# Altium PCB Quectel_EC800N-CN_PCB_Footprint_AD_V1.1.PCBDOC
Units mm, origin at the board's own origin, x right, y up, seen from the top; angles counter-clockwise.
Board outline 152.4 x 101.6 mm, 2 copper layers (Top Layer, Bottom Layer); 1 components, 0 nets, 94 pads, 0 vias.
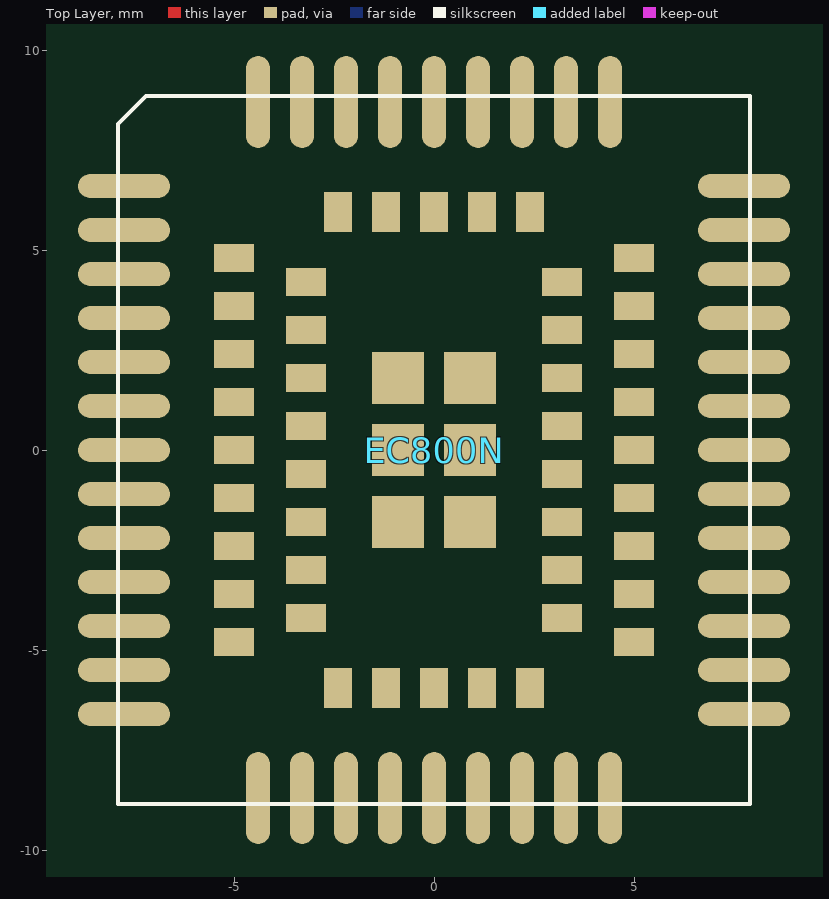
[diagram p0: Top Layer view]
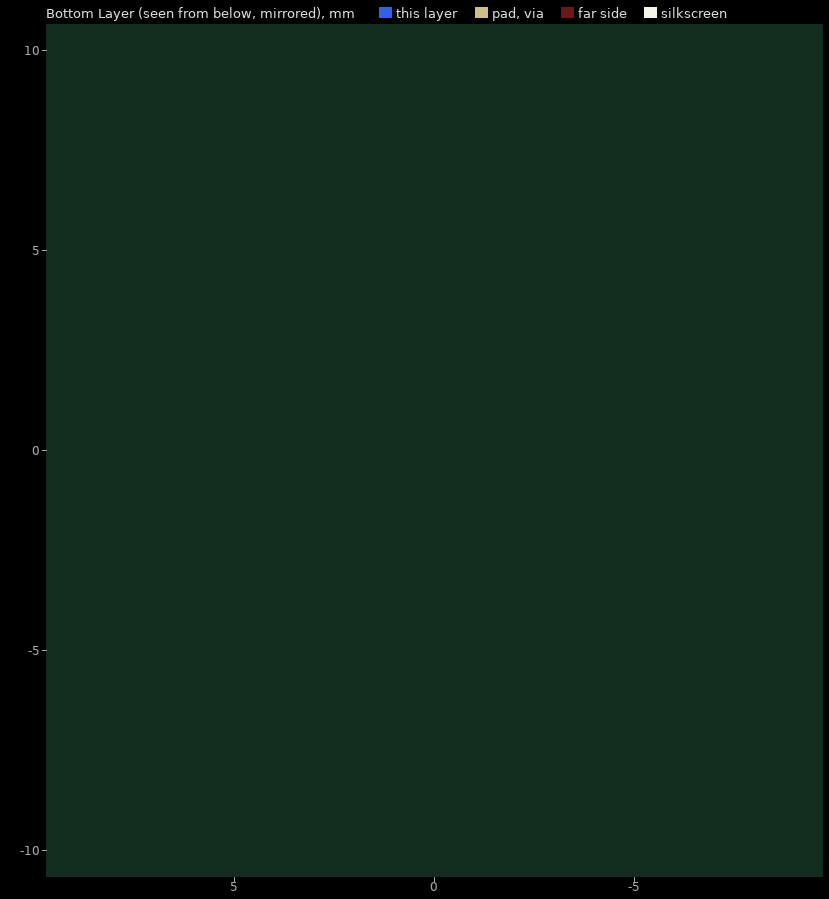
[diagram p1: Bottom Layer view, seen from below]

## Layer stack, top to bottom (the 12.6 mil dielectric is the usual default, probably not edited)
Top Solder: solder mask 0.0102, Solder Resist, Dk 3.5
Top Layer: signal copper 0.0356
Dielectric1: dielectric 0.32, FR-4, Dk 4.8
Bottom Layer: signal copper 0.0356
Bottom Solder: solder mask 0.0102, Solder Resist, Dk 3.5

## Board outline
-50.546,-45.466 101.854,-45.466 101.854,56.134 -50.546,56.134

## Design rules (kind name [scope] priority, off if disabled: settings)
Clearance [All] p1: gap=0.254 ignorepadtopadclearanceinfootprint=FALSE except(0: Arc-Hole Track-Hole SMDPad-Hole THPad-Hole Via-Hole Fill-Hole Poly-Hole Region-Hole Text-Hole)
FabricationTestPointUsage TestPointUsage [All] p1: valid=0 allowmultiple=FALSE
FabricationTestpoint Testpoint [All] p1: side=3 testpointundercomponent=TRUE minsize=1.016 maxsize=2.54 preferedsize=1.524 minholesize=0 maxholesize=1.016 preferedholesize=0.813 testpointgrid=0.025 allowsidetop=TRUE allowsidebottom=TRUE usegrid=TRUE gridtolerance=0
PolygonConnect [All] p1: connectstyle=Relief reliefconductorwidth=0.254 reliefentries=4 polygonreliefangle="90 Angle" airgapwidth=0.254
RoutingVias [All] p1: holewidth=0.711 width=1.27 viastyle="Through Hole" minholewidth=0.711 minwidth=1.27 maxholewidth=0.711 maxwidth=1.27
SolderMaskExpansion [All] p1: expansion=0.102
Width [All] p1: maxlimit=0.254 minlimit=0.254 preferedwidth=0.254
28 further rules are at their usual default settings.

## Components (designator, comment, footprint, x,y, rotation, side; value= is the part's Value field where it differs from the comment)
EC800N "Comment" EC800N 0,0 r0 top

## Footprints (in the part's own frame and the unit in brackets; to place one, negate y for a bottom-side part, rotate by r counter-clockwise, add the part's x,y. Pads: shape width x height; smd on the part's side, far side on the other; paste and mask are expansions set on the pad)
EC800N [mm] "EC800N-CN Moudle 94PIN 15.8X17.7mm H2.4mm RO"
  oval 2.3x0.6 smd mask+0.05: 1(-7.75,6.6) 2(-7.75,5.5) 3(-7.75,4.4) 4(-7.75,3.3) 5(-7.75,2.2) 6(-7.75,1.1) 7(-7.75,0) 8(-7.75,-1.1) 9(-7.75,-2.2) 10(-7.75,-3.3) 11(-7.75,-4.4) 12(-7.75,-5.5) 13(-7.75,-6.6) 23(7.75,-6.6) 24(7.75,-5.5) 25(7.75,-4.4) 26(7.75,-3.3) 27(7.75,-2.2) 28(7.75,-1.1) 29(7.75,0) 30(7.75,1.1) 31(7.75,2.2) 32(7.75,3.3) 33(7.75,4.4) 34(7.75,5.5) 35(7.75,6.6)
  oval 0.6x2.3 smd mask+0.05: 14(-4.4,-8.7) 15(-3.3,-8.7) 16(-2.2,-8.7) 17(-1.1,-8.7) 18(0,-8.7) 19(1.1,-8.7) 20(2.2,-8.7) 21(3.3,-8.7) 22(4.4,-8.7) 36(4.4,8.7) 37(3.3,8.7) 38(2.2,8.7) 39(1.1,8.7) 40(0,8.7) 41(-1.1,8.7) 42(-2.2,8.7) 43(-3.3,8.7) 44(-4.4,8.7)
  rect 1x0.7 smd mask+0.05: 45(-5,4.8) 46(-5,3.6) 47(-5,2.4) 48(-5,1.2) 49(-5,0) 50(-5,-1.2) 51(-5,-2.4) 52(-5,-3.6) 53(-5,-4.8) 59(5,-4.8) 60(5,-3.6) 61(5,-2.4) 62(5,-1.2) 63(5,0) 64(5,1.2) 65(5,2.4) 66(5,3.6) 67(5,4.8) 73(-3.2,4.2) 74(-3.2,3) 75(-3.2,1.8) 76(-3.2,0.6) 77(-3.2,-0.6) 78(-3.2,-1.8) 79(-3.2,-3) 80(-3.2,-4.2) 81(3.2,-4.2) 82(3.2,-3) 83(3.2,-1.8) 84(3.2,-0.6) 85(3.2,0.6) 86(3.2,1.8) 87(3.2,3) 88(3.2,4.2)
  rect 0.7x1 smd mask+0.05: 54(-2.4,-5.95) 55(-1.2,-5.95) 56(0,-5.95) 57(1.2,-5.95) 58(2.4,-5.95) 68(2.4,5.95) 69(1.2,5.95) 70(0,5.95) 71(-1.2,5.95) 72(-2.4,5.95)
  rect 1.3x1.3 smd mask+0.05: 89(-0.9,1.8) 90(-0.9,0) 91(-0.9,-1.8) 92(0.9,-1.8) 93(0.9,0) 94(0.9,1.8)
  silkscreen extent -7.9,-8.85 7.9,8.85

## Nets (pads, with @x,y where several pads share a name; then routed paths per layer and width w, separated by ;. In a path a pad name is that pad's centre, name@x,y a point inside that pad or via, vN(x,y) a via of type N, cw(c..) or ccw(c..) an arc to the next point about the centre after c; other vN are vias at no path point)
pads on no net: EC800N.1 EC800N.2 EC800N.3 EC800N.4 EC800N.5 EC800N.6 EC800N.7 EC800N.8 EC800N.9 EC800N.10 EC800N.11 EC800N.12 EC800N.13 EC800N.14 EC800N.15 EC800N.16 EC800N.17 EC800N.18 EC800N.19 EC800N.20 EC800N.21 EC800N.22 EC800N.23 EC800N.24 EC800N.25 EC800N.26 EC800N.27 EC800N.28 EC800N.29 EC800N.30 EC800N.31 EC800N.32 EC800N.33 EC800N.34 EC800N.35 EC800N.36 EC800N.37 EC800N.38 EC800N.39 EC800N.40 EC800N.41 EC800N.42 EC800N.43 EC800N.44 EC800N.45 EC800N.46 EC800N.47 EC800N.48 EC800N.49 EC800N.50 EC800N.51 EC800N.52 EC800N.53 EC800N.54 EC800N.55 EC800N.56 EC800N.57 EC800N.58 EC800N.59 EC800N.60 EC800N.61 EC800N.62 EC800N.63 EC800N.64 EC800N.65 EC800N.66 EC800N.67 EC800N.68 EC800N.69 EC800N.70 EC800N.71 EC800N.72 EC800N.73 EC800N.74 EC800N.75 EC800N.76 EC800N.77 EC800N.78 EC800N.79 EC800N.80 EC800N.81 EC800N.82 EC800N.83 EC800N.84 EC800N.85 EC800N.86 EC800N.87 EC800N.88 EC800N.89 EC800N.90 EC800N.91 EC800N.92 EC800N.93 EC800N.94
